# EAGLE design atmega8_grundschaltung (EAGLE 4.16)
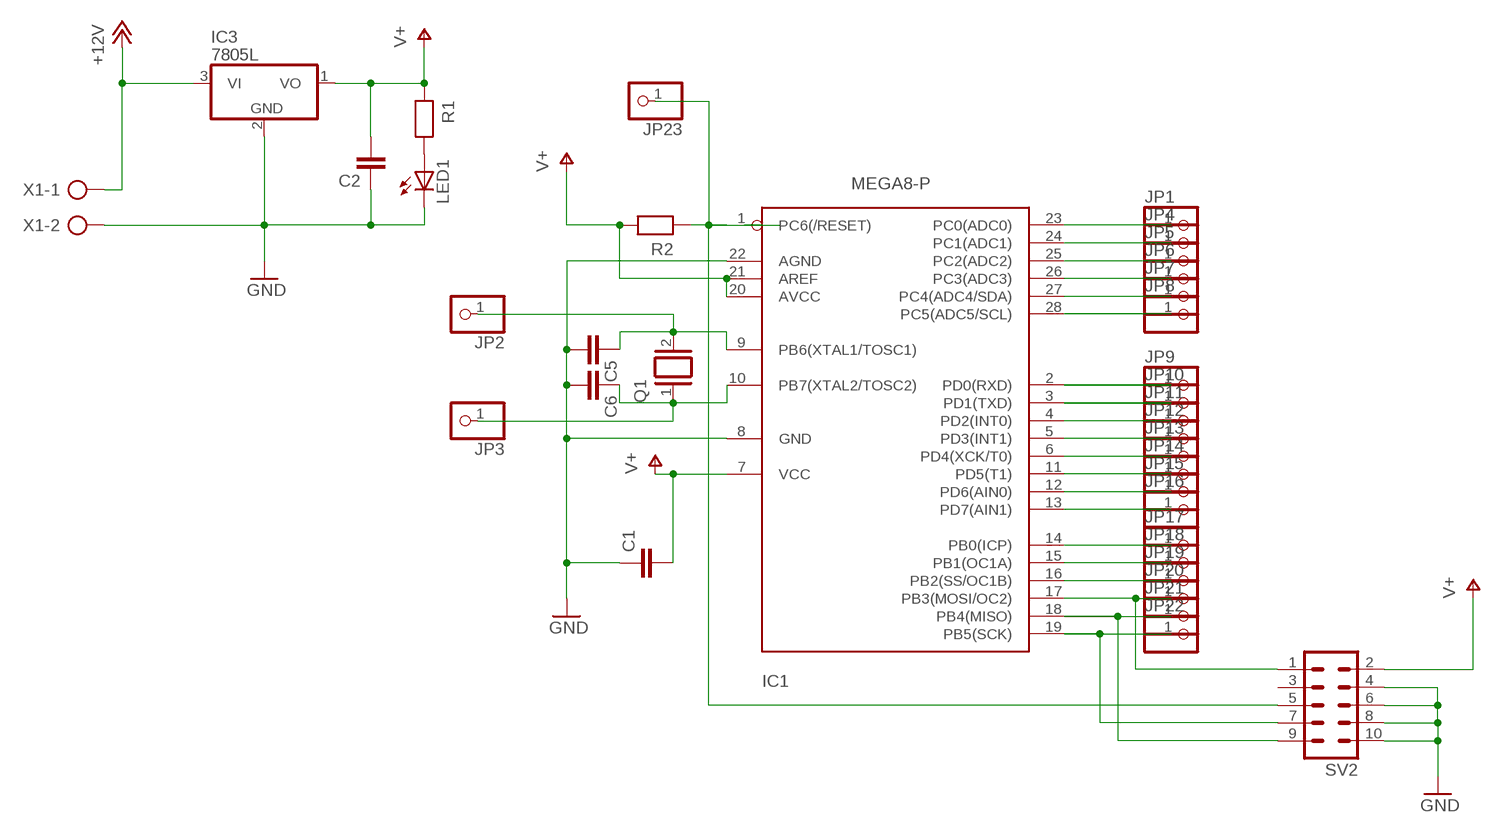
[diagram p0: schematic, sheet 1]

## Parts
C1  C2,5-3  [C2.5-3]
C2  C2.5/5  [C2.5-5]
C5  C2.5/5  [C2.5-5]
C6  C2.5/5  [C2.5-5]
IC1  MEGA8-P  [DIL28-3]
IC3  7805L  [TO92]
JP1  PINHD-1X1  [1X01]
JP2  PINHD-1X1  [1X01]
JP3  PINHD-1X1  [1X01]
JP4  PINHD-1X1  [1X01]
JP5  PINHD-1X1  [1X01]
JP6  PINHD-1X1  [1X01]
JP7  PINHD-1X1  [1X01]
JP8  PINHD-1X1  [1X01]
JP9  PINHD-1X1  [1X01]
JP10  PINHD-1X1  [1X01]
JP11  PINHD-1X1  [1X01]
JP12  PINHD-1X1  [1X01]
JP13  PINHD-1X1  [1X01]
JP14  PINHD-1X1  [1X01]
JP15  PINHD-1X1  [1X01]
JP16  PINHD-1X1  [1X01]
JP17  PINHD-1X1  [1X01]
JP18  PINHD-1X1  [1X01]
JP19  PINHD-1X1  [1X01]
JP20  PINHD-1X1  [1X01]
JP21  PINHD-1X1  [1X01]
JP22  PINHD-1X1  [1X01]
JP23  PINHD-1X1  [1X01]
LED1  LED3MM  [LED3MM]
Q1  XTAL/S  [QS]
R1  RESEU-7,5  [R-7,5]
R2  RESEU-7,5  [R-7,5]
SV2  ML10  [ML10]
X1  AK500/2  [AK500/2]

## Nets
+12V: IC3.3(VI) X1.1
GND: C1.1 C2.1 C5.2 C6.2 IC1.8(GND) IC1.22(AGND) IC3.2(GND) LED1.K(C) SV2.4 SV2.6 SV2.8 SV2.10 X1.2
N$1: C5.1 IC1.9(PB6(XTAL1/TOSC1)) JP2.1 Q1.2
N$2: C6.1 IC1.10(PB7(XTAL2/TOSC2)) JP3.1 Q1.1
N$3: IC1.23(PC0(ADC0)) JP1.1
N$4: LED1.A R1.2
N$5: IC1.24(PC1(ADC1)) JP4.1
N$6: IC1.25(PC2(ADC2)) JP5.1
N$7: IC1.26(PC3(ADC3)) JP6.1
N$8: IC1.27(PC4(ADC4/SDA)) JP7.1
N$9: IC1.28(PC5(ADC5/SCL)) JP8.1
N$10: IC1.4(PD2(INT0)) JP11.1
N$11: IC1.5(PD3(INT1)) JP12.1
N$12: IC1.6(PD4(XCK/T0)) JP13.1
N$17: IC1.3(PD1(TXD)) JP10.1
N$18: IC1.2(PD0(RXD)) JP9.1
N$23: IC1.11(PD5(T1)) JP14.1
N$24: IC1.1(PC6(/RESET)) JP23.1 R2.1 SV2.5
N$25: IC1.12(PD6(AIN0)) JP15.1
N$26: IC1.13(PD7(AIN1)) JP16.1
N$27: IC1.14(PB0(ICP)) JP17.1
N$28: IC1.17(PB3(MOSI/OC2)) JP20.1 SV2.1
N$29: IC1.19(PB5(SCK)) JP22.1 SV2.7
N$30: IC1.18(PB4(MISO)) JP21.1 SV2.9
N$31: IC1.15(PB1(OC1A)) JP18.1
N$32: IC1.16(PB2(SS/OC1B)) JP19.1
V+: C1.2 C2.2 IC1.7(VCC) IC1.20(AVCC) IC1.21(AREF) IC3.1(VO) R1.1 R2.2 SV2.2
Unconnected: SV2.3

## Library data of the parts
C1 C2 C5 C6 = capacitor-wima:C: CAPACITOR
IC1 = avr:MEGA8-P: MICROCONTROLLER 8 Kbytes FLASH 1 kbytes SRAM 512 bytes EEPROM USART 4-channel 10 bit ADC 2-channel 8 bit ADC
IC3 = linear:78*: Positive VOLTAGE REGULATOR Source: http://cache.national.com/ds/LM/LM78L05.pdf http://www.fairchildsemi.com/ds/LM/LM7805.pdf
JP1-JP23 = pinhead:PINHD-1X1: PIN HEADER
LED1 = led:LED: LED
Q1 = special:XTAL/S: CRYSTAL
R1 R2 = discrete:RESEU-7,5
SV2 = con-harting-ml:ML10: HARTING
X1 = con-ptr500:AK500/2: CONNECTOR

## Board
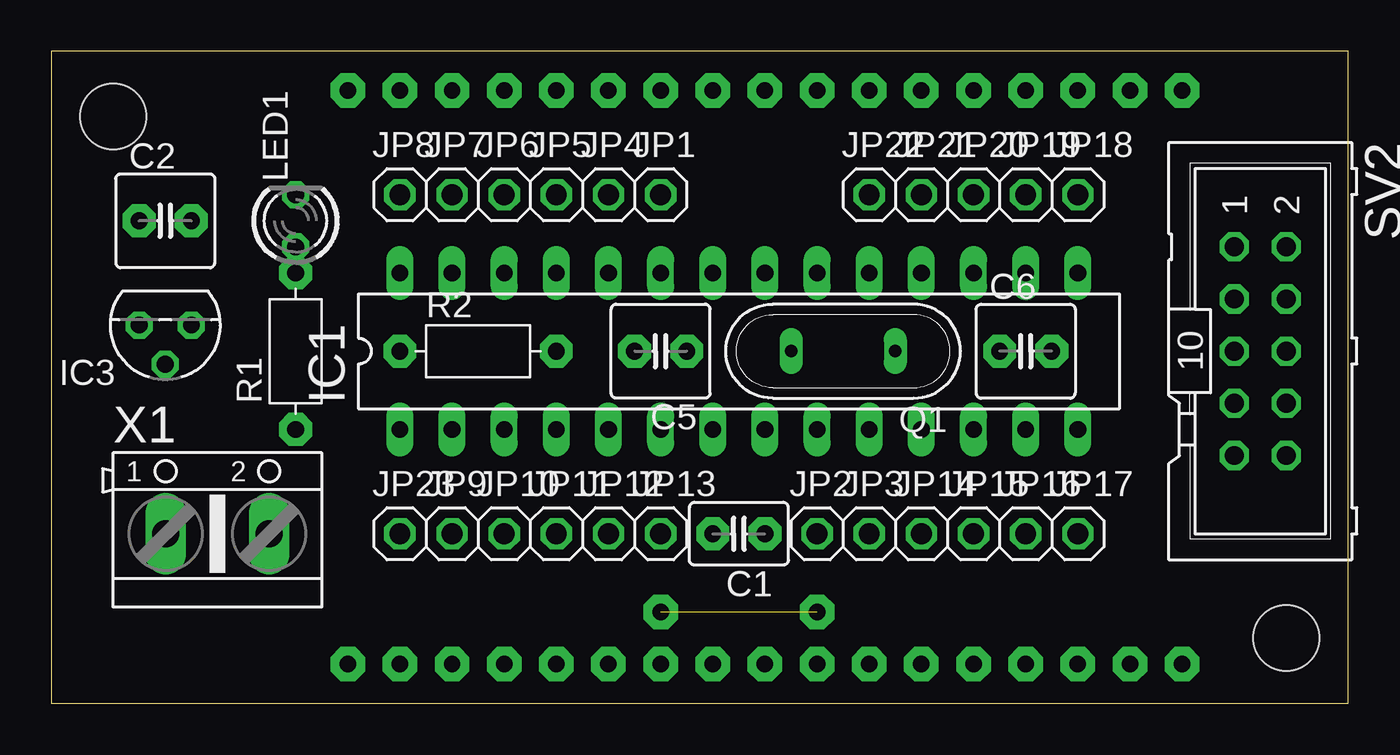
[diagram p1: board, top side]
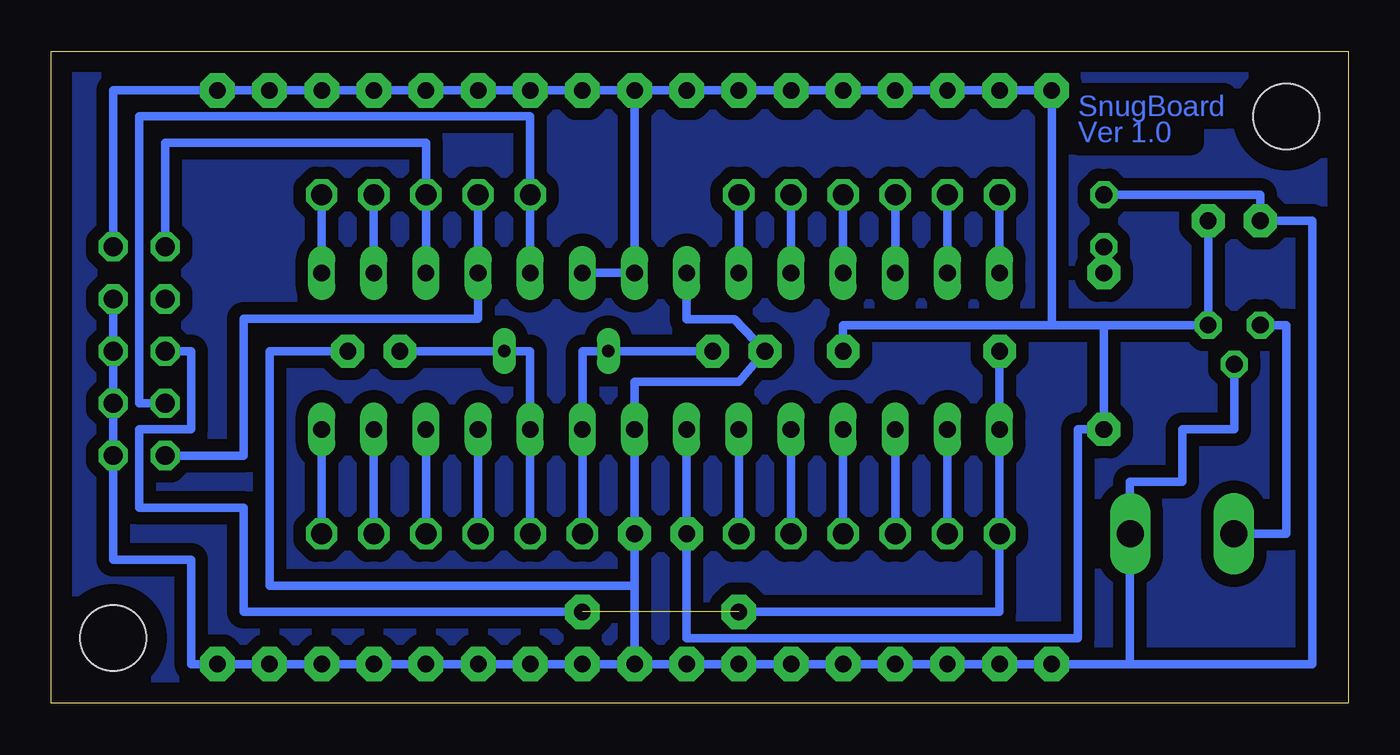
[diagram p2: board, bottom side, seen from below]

Size 63.17 x 31.74 mm. Coordinates in mm from the lower left corner, seen from the top.
Outline: 0,0 63.17,0 63.17,31.74 0,31.74 0,0
Copper layers (1*16): Top 0.035mm / dielectric 1.5mm / Bottom 0.035mm
Design rules "default": minimum track width 10mil, minimum drill 24mil, track to track 8mil, track to pad 8mil, pad to pad 8mil, via to via 8mil, smd to smd 8mil, copper to edge 40mil, drill to drill 8mil, minimum pad ring 10mil, minimum via ring 8mil, stop-mask expansion 4mil, vias tented up to drill 0mil, thermal gap 10mil
Holes 3.2 mm at 3.01,28.57 60.16,3.17

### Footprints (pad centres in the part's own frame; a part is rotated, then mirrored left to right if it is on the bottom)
C2.5-3 = drill 0.813 pad 1.6 octagon: 1 -1.27,0; 2 1.27,0
C2.5-5 = drill 0.813 pad 1.6 octagon: 1 -1.27,0; 2 1.27,0
DIL28-3 = drill 0.813 long: 1 -16.51,-3.81; 2 -13.97,-3.81; 3 -11.43,-3.81; 4 -8.89,-3.81; 5 -6.35,-3.81; 6 -3.81,-3.81; 7 -1.27,-3.81; 8 1.27,-3.81; 9 3.81,-3.81; 10 6.35,-3.81; 11 8.89,-3.81; 12 11.43,-3.81; 13 13.97,-3.81; 14 16.51,-3.81; 15 16.51,3.81; 16 13.97,3.81; 17 11.43,3.81; 18 8.89,3.81; 19 6.35,3.81; 20 3.81,3.81; 21 1.27,3.81; 22 -1.27,3.81; 23 -3.81,3.81; 24 -6.35,3.81; 25 -8.89,3.81; 26 -11.43,3.81; 27 -13.97,3.81; 28 -16.51,3.81
TO92 = drill 0.813 octagon: 1 -1.27,0; 2 0,1.905; 3 1.27,0
1X01 = drill 1.016 octagon: 1 0,0
LED3MM = drill 0.813 octagon: A -1.27,0; K 1.27,0
QS = drill 0.61 long: 1 -2.54,0; 2 2.54,0
R-7,5 = drill 0.813 pad 1.6 octagon: 1 -3.81,0; 2 3.81,0
ML10 = drill 0.914 octagon: 1 -5.08,-1.27; 2 -5.08,1.27; 3 -2.54,-1.27; 4 -2.54,1.27; 5 0,-1.27; 6 0,1.27; 7 2.54,-1.27; 8 2.54,1.27; 9 5.08,-1.27; 10 5.08,1.27
AK500/2 = drill 1.321 long: 1 -2.515,0; 2 2.515,0

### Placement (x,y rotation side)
C1  33.49,8.25 180 top
C2  5.55,23.49 0 top
C5  29.68,17.14 180 top
C6  47.46,17.14 0 top
IC1  33.49,17.14 0 top
IC3  5.55,18.41 180 top
JP1  29.68,24.76 0 top
JP2  37.3,8.25 0 top
JP3  39.84,8.25 0 top
JP4  27.14,24.76 0 top
JP5  24.6,24.76 0 top
JP6  22.06,24.76 0 top
JP7  19.52,24.76 0 top
JP8  16.98,24.76 0 top
JP9  19.52,8.25 0 top
JP10  22.06,8.25 0 top
JP11  24.6,8.25 0 top
JP12  27.14,8.25 0 top
JP13  29.68,8.25 0 top
JP14  42.38,8.25 0 top
JP15  44.92,8.25 0 top
JP16  47.46,8.25 0 top
JP17  50,8.25 0 top
JP18  50,24.76 0 top
JP19  47.46,24.76 0 top
JP20  44.92,24.76 0 top
JP21  42.38,24.76 0 top
JP22  39.84,24.76 0 top
JP23  16.98,8.25 0 top
LED1  11.9,23.49 90 top
Q1  38.57,17.14 180 top
R1  11.9,17.14 90 top
R2  20.79,17.14 0 top
SV2  58.89,17.14 270 top
X1  8.09,8.25 0 top

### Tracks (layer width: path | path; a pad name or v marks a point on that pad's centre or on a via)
+12V
  Bottom 0.406: X1.1 3.01,8.25 3.01,18.41 IC3.3
GND  (via drill 0.8 pad 1.68)
  Bottom 0.406: 10.63,9.52 X1.2 10.63,8.25 | 10.63,1.9 v14.44,1.9 v16.98,1.9 v19.52,1.9 v22.06,1.9 v24.6,1.9 v27.14,1.9 v29.68,1.9 v32.22,1.9 v34.76,1.9 | v34.76,1.9 34.76,5.71 | 34.76,5.71 C1.1 IC1.8 34.76,15.64 29.68,15.64 C5.2 29.9,18.69 32.22,18.69 IC1.22 | v34.76,1.9 v37.3,1.9 v39.84,1.9 v42.38,1.9 v44.92,1.9 v47.46,1.9 v50,1.9 v52.54,1.9 v55.08,1.9 56.35,1.9 56.35,6.98 60.16,6.98 SV2.10 SV2.8 SV2.6 SV2.4 | 10.63,1.9 1.74,1.9 1.74,23.49 C2.1 4.28,24.76 LED1.K | C6.2 52.54,17.14 52.54,5.71 34.76,5.71 | IC3.2 5.55,13.33 8.09,13.33 8.09,10.79 10.63,10.79 10.63,8.25 | 10.63,1.9 10.63,8.25
N$1
  Bottom 0.406: 37.3,17.14 Q1.2 | 37.3,17.14 IC1.9 JP2.1 | 37.3,17.14 C5.1
N$2
  Bottom 0.406: JP3.1 IC1.10 39.84,17.14 Q1.1 C6.1
N$3
  Bottom 0.406: IC1.23 JP1.1
N$4
  Bottom 0.406: LED1.A R1.2
N$5
  Bottom 0.406: IC1.24 JP4.1
N$6
  Bottom 0.406: IC1.25 JP5.1
N$7
  Bottom 0.406: IC1.26 JP6.1
N$8
  Bottom 0.406: IC1.27 JP7.1
N$9
  Bottom 0.406: IC1.28 JP8.1
N$10
  Bottom 0.406: JP11.1 IC1.4
N$11
  Bottom 0.406: JP12.1 IC1.5
N$12
  Bottom 0.406: JP13.1 IC1.6
N$13  (via drill 0.8 pad 1.68)
  other vias: 37.3,4.44
N$14  (via drill 0.8 pad 1.68)
  other vias: 29.68,4.44
N$15
  pour Bottom (isolate 0.61): 0.47,31.11 62.7,31.11 62.7,0.63 0.47,0.63
N$17
  Bottom 0.406: JP10.1 IC1.3
N$18
  Bottom 0.406: JP9.1 IC1.2
N$23
  Bottom 0.406: JP14.1 IC1.11
N$24  (via drill 0.8)  (1 unrouted)
  Bottom 0.406: JP23.1 IC1.1 R2.1 16.98,4.44 v29.68,4.44 | SV2.5 56.35,17.14 56.35,13.33 58.89,13.33 58.89,9.52 53.81,9.52 53.81,4.44 v37.3,4.44
N$25
  Bottom 0.406: JP15.1 IC1.12
N$26
  Bottom 0.406: JP16.1 IC1.13
N$27
  Bottom 0.406: JP17.1 IC1.14
N$28
  Bottom 0.406: IC1.17 JP20.1 44.92,27.3 57.62,27.3 SV2.1
N$29
  Bottom 0.406: JP22.1 IC1.19 39.84,28.57 58.89,28.57 58.89,14.6 SV2.7
N$30
  Bottom 0.406: JP21.1 IC1.18 42.38,18.72 53.81,18.72 53.81,12.06 SV2.9
N$31
  Bottom 0.406: IC1.15 JP18.1
N$32
  Bottom 0.406: IC1.16 JP19.1
V+  (via drill 0.8 pad 1.68)
  Bottom 0.406: C2.2 IC3.1 11.9,18.41 | R2.2 24.6,18.41 14.44,18.41 | SV2.2 60.16,29.84 v55.08,29.84 v52.54,29.84 v50,29.84 v47.46,29.84 v44.92,29.84 v42.38,29.84 v39.84,29.84 v37.3,29.84 v34.76,29.84 | v34.76,29.84 v32.22,29.84 v29.68,29.84 v27.14,29.84 v24.6,29.84 v22.06,29.84 v19.52,29.84 v16.98,29.84 v14.44,29.84 14.44,18.41 | IC1.20 IC1.21 v34.76,29.84 | 11.9,18.41 R1.1 13.17,13.33 13.17,3.17 32.22,3.17 C1.2 IC1.7 | 11.9,18.41 14.44,18.41

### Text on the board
Bottom: SnugBoard | Ver 1.0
